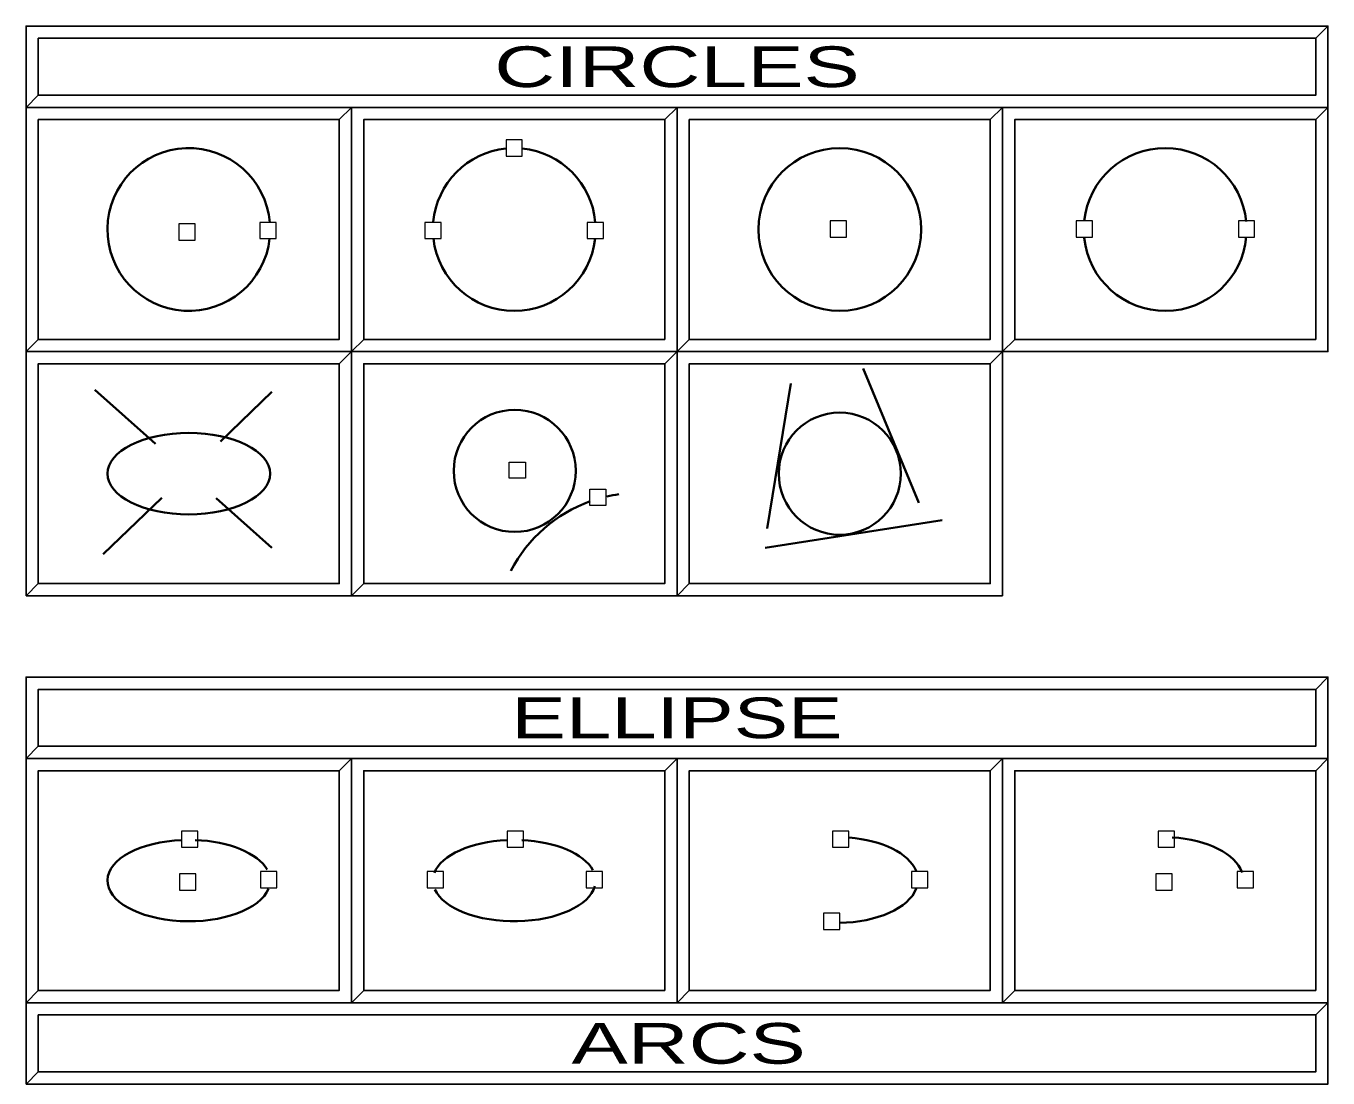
# Model space of a CAD drawing. Extents: x 95906.8 to 95923.6, y 90964.8 to 90972.8.
# Drawn here: x 95910.832 to 95912.432, y 90968.669 to 90969.962 of the extents above; entities that cross this region are included whole.
import ezdxf
from ezdxf.enums import TextEntityAlignment as Align

# ---------------------------------------------------------------- set-up
doc = ezdxf.new("R2010")
doc.units = 0
doc.header["$LTSCALE"] = 0.019
doc.linetypes.add('MEDIUM_DASHED', pattern=[4.5, 3, -1.5])
for name, color, linetype, lineweight in [('1', 7, 'Continuous', 25), ('11', 7, 'Continuous', 25), ('12', 7, 'Continuous', 25), ('17', 7, 'Continuous', 25), ('2', 7, 'Continuous', 13), ('3', 7, 'Continuous', 25), ('6', 7, 'Continuous', 35), ('7', 7, 'Continuous', 35)]:
    doc.layers.add(name, color=color, linetype=linetype, lineweight=lineweight)

msp = doc.modelspace()

# ---------------------------------------------------------------- linework, layer by layer
at = {"layer": '1'}
for points in [[(95910.8318, 90969.8617), (95912.4318, 90969.8617), (95912.4318, 90969.9617), (95910.8318, 90969.9617)], [(95910.8318, 90969.5617), (95911.2318, 90969.5617), (95911.2318, 90969.8617), (95910.8318, 90969.8617)], [(95911.2318, 90969.5617), (95911.6318, 90969.5617), (95911.6318, 90969.8617), (95911.2318, 90969.8617)], [(95911.6318, 90969.5617), (95912.0318, 90969.5617), (95912.0318, 90969.8617), (95911.6318, 90969.8617)], [(95912.0318, 90969.5617), (95912.4318, 90969.5617), (95912.4318, 90969.8617), (95912.0318, 90969.8617)], [(95910.8318, 90969.2617), (95911.2318, 90969.2617), (95911.2318, 90969.5617), (95910.8318, 90969.5617)], [(95911.2318, 90969.2617), (95911.6318, 90969.2617), (95911.6318, 90969.5617), (95911.2318, 90969.5617)], [(95911.6318, 90969.2617), (95912.0318, 90969.2617), (95912.0318, 90969.5617), (95911.6318, 90969.5617)], [(95910.8318, 90969.0617), (95912.4318, 90969.0617), (95912.4318, 90969.1617), (95910.8318, 90969.1617)], [(95910.8318, 90968.7617), (95911.2318, 90968.7617), (95911.2318, 90969.0617), (95910.8318, 90969.0617)], [(95911.2318, 90968.7617), (95911.6318, 90968.7617), (95911.6318, 90969.0617), (95911.2318, 90969.0617)], [(95911.6318, 90968.7617), (95912.0318, 90968.7617), (95912.0318, 90969.0617), (95911.6318, 90969.0617)], [(95912.0318, 90968.7617), (95912.4318, 90968.7617), (95912.4318, 90969.0617), (95912.0318, 90969.0617)], [(95910.8318, 90968.6617), (95912.4318, 90968.6617), (95912.4318, 90968.7617), (95910.8318, 90968.7617)]]:
    msp.add_lwpolyline(points, close=True, dxfattribs=at)
at = {"layer": '11'}
for points in [[(95911.2468, 90969.5767), (95911.6168, 90969.5767), (95911.6168, 90969.8467), (95911.2468, 90969.8467)], [(95911.6468, 90969.5767), (95912.0168, 90969.5767), (95912.0168, 90969.8467), (95911.6468, 90969.8467)], [(95912.0468, 90969.5767), (95912.4168, 90969.5767), (95912.4168, 90969.8467), (95912.0468, 90969.8467)], [(95910.8468, 90969.2767), (95911.2168, 90969.2767), (95911.2168, 90969.5467), (95910.8468, 90969.5467)], [(95911.2468, 90969.2767), (95911.6168, 90969.2767), (95911.6168, 90969.5467), (95911.2468, 90969.5467)], [(95911.6468, 90969.2767), (95912.0168, 90969.2767), (95912.0168, 90969.5467), (95911.6468, 90969.5467)], [(95911.2468, 90968.7767), (95911.6168, 90968.7767), (95911.6168, 90969.0467), (95911.2468, 90969.0467)], [(95911.6468, 90968.7767), (95912.0168, 90968.7767), (95912.0168, 90969.0467), (95911.6468, 90969.0467)], [(95912.0468, 90968.7767), (95912.4168, 90968.7767), (95912.4168, 90969.0467), (95912.0468, 90969.0467)]]:
    msp.add_lwpolyline(points, close=True, dxfattribs=at)
at = {"layer": '12'}
for points in [[(95910.8468, 90969.5767), (95911.2168, 90969.5767), (95911.2168, 90969.8467), (95910.8468, 90969.8467)], [(95910.8468, 90968.7767), (95911.2168, 90968.7767), (95911.2168, 90969.0467), (95910.8468, 90969.0467)]]:
    msp.add_lwpolyline(points, close=True, dxfattribs=at)
at = {"layer": '17'}
for points in [[(95910.8468, 90969.8767), (95912.4168, 90969.8767), (95912.4168, 90969.9467), (95910.8468, 90969.9467)], [(95910.8468, 90969.0767), (95912.4168, 90969.0767), (95912.4168, 90969.1467), (95910.8468, 90969.1467)], [(95910.8468, 90968.6767), (95912.4168, 90968.6767), (95912.4168, 90968.7467), (95910.8468, 90968.7467)]]:
    msp.add_lwpolyline(points, close=True, dxfattribs=at)
at = {"layer": '2'}
for points in [[(95910.8318, 90969.9617), (95910.8318, 90969.8617), (95910.8468, 90969.8767), (95910.8468, 90969.9467), (95912.4168, 90969.9467), (95912.4318, 90969.9617)], [(95910.8318, 90969.8617), (95910.8318, 90969.5617), (95910.8468, 90969.5767), (95910.8468, 90969.8467), (95911.2168, 90969.8467), (95911.2318, 90969.8617)], [(95911.2318, 90969.8617), (95911.2318, 90969.5617), (95911.2468, 90969.5767), (95911.2468, 90969.8467), (95911.6168, 90969.8467), (95911.6318, 90969.8617)], [(95911.6318, 90969.8617), (95911.6318, 90969.5617), (95911.6468, 90969.5767), (95911.6468, 90969.8467), (95912.0168, 90969.8467), (95912.0318, 90969.8617)], [(95912.0318, 90969.8617), (95912.0318, 90969.5617), (95912.0468, 90969.5767), (95912.0468, 90969.8467), (95912.4168, 90969.8467), (95912.4318, 90969.8617)], [(95910.8318, 90969.5617), (95910.8318, 90969.2617), (95910.8468, 90969.2767), (95910.8468, 90969.5467), (95911.2168, 90969.5467), (95911.2318, 90969.5617)], [(95911.2318, 90969.5617), (95911.2318, 90969.2617), (95911.2468, 90969.2767), (95911.2468, 90969.5467), (95911.6168, 90969.5467), (95911.6318, 90969.5617)], [(95911.6318, 90969.5617), (95911.6318, 90969.2617), (95911.6468, 90969.2767), (95911.6468, 90969.5467), (95912.0168, 90969.5467), (95912.0318, 90969.5617)], [(95910.8318, 90969.1617), (95910.8318, 90969.0617), (95910.8468, 90969.0767), (95910.8468, 90969.1467), (95912.4168, 90969.1467), (95912.4318, 90969.1617)], [(95910.8318, 90969.0617), (95910.8318, 90968.7617), (95910.8468, 90968.7767), (95910.8468, 90969.0467), (95911.2168, 90969.0467), (95911.2318, 90969.0617)], [(95911.2318, 90969.0617), (95911.2318, 90968.7617), (95911.2468, 90968.7767), (95911.2468, 90969.0467), (95911.6168, 90969.0467), (95911.6318, 90969.0617)], [(95911.6318, 90969.0617), (95911.6318, 90968.7617), (95911.6468, 90968.7767), (95911.6468, 90969.0467), (95912.0168, 90969.0467), (95912.0318, 90969.0617)], [(95912.0318, 90969.0617), (95912.0318, 90968.7617), (95912.0468, 90968.7767), (95912.0468, 90969.0467), (95912.4168, 90969.0467), (95912.4318, 90969.0617)], [(95910.8318, 90968.7617), (95910.8318, 90968.6617), (95910.8468, 90968.6767), (95910.8468, 90968.7467), (95912.4168, 90968.7467), (95912.4318, 90968.7617)]]:
    msp.add_lwpolyline(points, close=True, dxfattribs=at)
at = {"layer": '3'}
for points in [[(95910.8318, 90969.8617), (95912.4318, 90969.8617), (95912.4318, 90969.9617), (95912.4168, 90969.9467), (95912.4168, 90969.8767), (95910.8468, 90969.8767)], [(95910.8318, 90969.5617), (95911.2318, 90969.5617), (95911.2318, 90969.8617), (95911.2168, 90969.8467), (95911.2168, 90969.5767), (95910.8468, 90969.5767)], [(95911.2318, 90969.5617), (95911.6318, 90969.5617), (95911.6318, 90969.8617), (95911.6168, 90969.8467), (95911.6168, 90969.5767), (95911.2468, 90969.5767)], [(95911.6318, 90969.5617), (95912.0318, 90969.5617), (95912.0318, 90969.8617), (95912.0168, 90969.8467), (95912.0168, 90969.5767), (95911.6468, 90969.5767)], [(95912.0318, 90969.5617), (95912.4318, 90969.5617), (95912.4318, 90969.8617), (95912.4168, 90969.8467), (95912.4168, 90969.5767), (95912.0468, 90969.5767)], [(95910.8318, 90969.2617), (95911.2318, 90969.2617), (95911.2318, 90969.5617), (95911.2168, 90969.5467), (95911.2168, 90969.2767), (95910.8468, 90969.2767)], [(95911.2318, 90969.2617), (95911.6318, 90969.2617), (95911.6318, 90969.5617), (95911.6168, 90969.5467), (95911.6168, 90969.2767), (95911.2468, 90969.2767)], [(95911.6318, 90969.2617), (95912.0318, 90969.2617), (95912.0318, 90969.5617), (95912.0168, 90969.5467), (95912.0168, 90969.2767), (95911.6468, 90969.2767)], [(95910.8318, 90969.0617), (95912.4318, 90969.0617), (95912.4318, 90969.1617), (95912.4168, 90969.1467), (95912.4168, 90969.0767), (95910.8468, 90969.0767)], [(95910.8318, 90968.7617), (95911.2318, 90968.7617), (95911.2318, 90969.0617), (95911.2168, 90969.0467), (95911.2168, 90968.7767), (95910.8468, 90968.7767)], [(95911.2318, 90968.7617), (95911.6318, 90968.7617), (95911.6318, 90969.0617), (95911.6168, 90969.0467), (95911.6168, 90968.7767), (95911.2468, 90968.7767)], [(95911.6318, 90968.7617), (95912.0318, 90968.7617), (95912.0318, 90969.0617), (95912.0168, 90969.0467), (95912.0168, 90968.7767), (95911.6468, 90968.7767)], [(95912.0318, 90968.7617), (95912.4318, 90968.7617), (95912.4318, 90969.0617), (95912.4168, 90969.0467), (95912.4168, 90968.7767), (95912.0468, 90968.7767)], [(95910.8318, 90968.6617), (95912.4318, 90968.6617), (95912.4318, 90968.7617), (95912.4168, 90968.7467), (95912.4168, 90968.6767), (95910.8468, 90968.6767)]]:
    msp.add_lwpolyline(points, close=True, dxfattribs=at)
at = {"layer": '6'}
for p, q in [((95911.9289, 90969.3757), (95911.8607, 90969.541)), ((95911.7426, 90969.3442), (95911.7715, 90969.5226)), ((95911.74, 90969.3206), (95911.9578, 90969.3547))]:
    msp.add_line(p, q, dxfattribs=at)
at = {"layer": '6', "linetype": 'MEDIUM_DASHED'}
for p, q in [((95910.9162, 90969.5148), (95911.1339, 90969.3206)), ((95910.9267, 90969.3127), (95911.1339, 90969.5121))]:
    msp.add_line(p, q, dxfattribs=at)
at = {"layer": '6', "lineweight": 13}
for points in [[(95911.4217, 90969.8019), (95911.4417, 90969.8019), (95911.4417, 90969.8219), (95911.4217, 90969.8219)], [(95911.0196, 90969.6985), (95911.0396, 90969.6985), (95911.0396, 90969.7185), (95911.0196, 90969.7185)], [(95911.1192, 90969.7005), (95911.1392, 90969.7005), (95911.1392, 90969.7205), (95911.1192, 90969.7205)], [(95911.3221, 90969.7005), (95911.3421, 90969.7005), (95911.3421, 90969.7205), (95911.3221, 90969.7205)], [(95911.5213, 90969.7005), (95911.5413, 90969.7005), (95911.5413, 90969.7205), (95911.5213, 90969.7205)], [(95911.82, 90969.7024), (95911.84, 90969.7024), (95911.84, 90969.7224), (95911.82, 90969.7224)], [(95912.1225, 90969.7024), (95912.1425, 90969.7024), (95912.1425, 90969.7224), (95912.1225, 90969.7224)], [(95912.3217, 90969.7024), (95912.3417, 90969.7024), (95912.3417, 90969.7224), (95912.3217, 90969.7224)], [(95911.4455, 90969.406), (95911.4255, 90969.406), (95911.4255, 90969.426), (95911.4455, 90969.426)], [(95911.5445, 90969.3727), (95911.5245, 90969.3727), (95911.5245, 90969.3927), (95911.5445, 90969.3927)], [(95911.023, 90968.9526), (95911.043, 90968.9526), (95911.043, 90968.9726), (95911.023, 90968.9726)], [(95911.423, 90968.9526), (95911.443, 90968.9526), (95911.443, 90968.9726), (95911.423, 90968.9726)], [(95911.823, 90968.9526), (95911.843, 90968.9526), (95911.843, 90968.9726), (95911.823, 90968.9726)], [(95912.223, 90968.9526), (95912.243, 90968.9526), (95912.243, 90968.9726), (95912.223, 90968.9726)], [(95911.0204, 90968.9001), (95911.0404, 90968.9001), (95911.0404, 90968.9201), (95911.0204, 90968.9201)], [(95911.1201, 90968.9027), (95911.1401, 90968.9027), (95911.1401, 90968.9227), (95911.1201, 90968.9227)], [(95911.3248, 90968.9027), (95911.3448, 90968.9027), (95911.3448, 90968.9227), (95911.3248, 90968.9227)], [(95911.5201, 90968.9027), (95911.5401, 90968.9027), (95911.5401, 90968.9227), (95911.5201, 90968.9227)], [(95911.9201, 90968.9027), (95911.9401, 90968.9027), (95911.9401, 90968.9227), (95911.9201, 90968.9227)], [(95912.2204, 90968.9001), (95912.2404, 90968.9001), (95912.2404, 90968.9201), (95912.2204, 90968.9201)], [(95912.3201, 90968.9027), (95912.3401, 90968.9027), (95912.3401, 90968.9227), (95912.3201, 90968.9227)], [(95911.8119, 90968.8517), (95911.8319, 90968.8517), (95911.8319, 90968.8717), (95911.8119, 90968.8717)]]:
    msp.add_lwpolyline(points, close=True, dxfattribs=at)
at = {"layer": '6'}
for centre, radius in [((95911.8318, 90969.7117), 0.1), ((95911.4324, 90969.4151), 0.075), ((95911.8318, 90969.4117), 0.075)]:
    msp.add_circle(centre, radius, dxfattribs=at)
for centre, radius, start, end in [((95911.0318, 90969.7117), 0.1, 4.8874, 353.6041), ((95911.4318, 90969.7117), 0.1, 95.8922, 174.6455), ((95911.4318, 90969.7117), 0.1, 5.1844, 84.3911), ((95912.2318, 90969.7117), 0.1, 5.5709, 173.9917), ((95911.4318, 90969.7117), 0.1, 186.3938, 353.698), ((95912.2318, 90969.7117), 0.1, 185.8843, 354.917), ((95911.5848, 90969.2113), 0.1768, 109.6854, 152.699), ((95911.5848, 90969.2113), 0.1768, 98.0074, 102.8294)]:
    msp.add_arc(centre, radius, start, end, dxfattribs=at)
msp.add_ellipse((95911.0318, 90969.4117), major_axis=(0.1, 0), ratio=0.5, dxfattribs=at)
for centre, major_axis, ratio, start_param, end_param in [((95911.0318, 90968.9117), (0.1, 0), 0.5, 1.652145, 6.081781), ((95911.0318, 90968.9117), (0.1, 0), 0.5, 0.273628, 1.493467), ((95911.4318, 90968.9117), (0.1, 0), 0.5, 1.662997, 2.947365), ((95911.4318, 90968.9117), (0.1, 0), 0.5, 0.260759, 1.478137), ((95911.8286, 90968.9124), (-0.0993, 0), 0.53093, 3.360642, 4.563617), ((95912.2285, 90968.9124), (-0.0993, 0), 0.53093, 3.321217, 4.591689), ((95911.4318, 90968.9117), (0.1, 0), 0.5, 3.359628, 6.146211), ((95911.8286, 90968.9124), (-0.0993, 0), 0.53093, 1.599791, 2.939476)]:
    msp.add_ellipse(centre, major_axis=major_axis, ratio=ratio, start_param=start_param, end_param=end_param, dxfattribs=at)

# ---------------------------------------------------------------- texts
at = {"layer": '7'}
for s, width, p in [('        CIRCLES        ', 1.55, (95911.6318, 90969.8867)), ('        ELLIPSE        ', 1.5, (95911.6318, 90969.0867)), ('          ARCS         ', 1.55, (95911.6317, 90968.6867))]:
    msp.add_text(s, height=0.04999, dxfattribs=dict(at, width=width)).set_placement(p, align=Align.CENTER)

doc.saveas('drawing.dxf')
